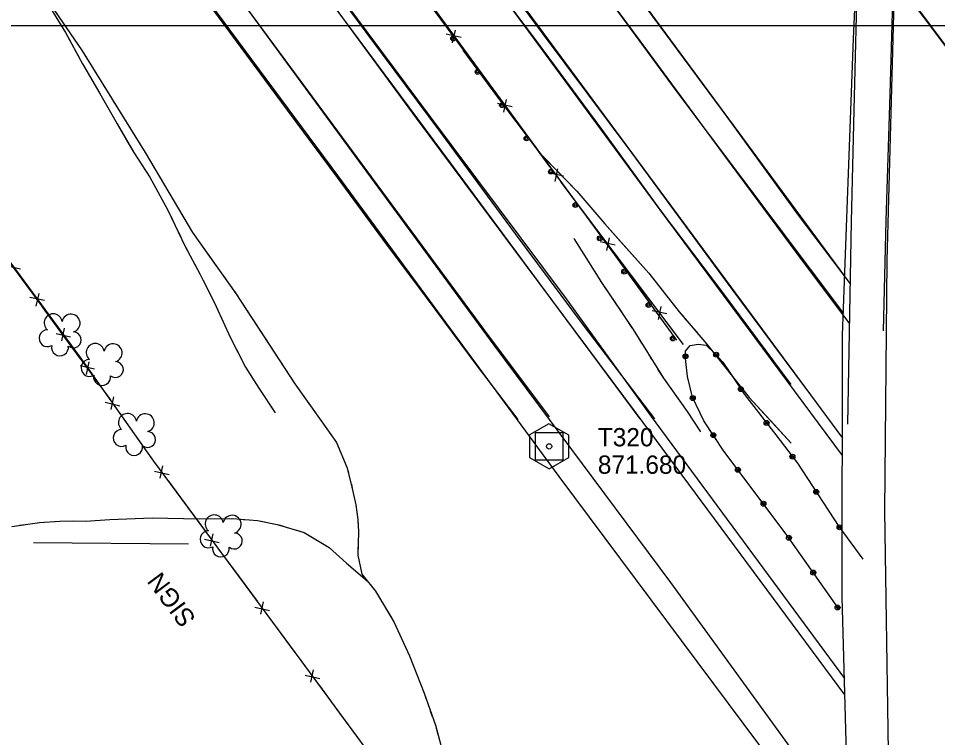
# Model space of a CAD drawing. Extents: x 353423 to 364002, y 127000 to 201942.
# Drawn here: x 361062.1 to 361364.1, y 129766.2 to 130002.3 of the extents above; entities that cross this region are included whole.
import ezdxf

# ---------------------------------------------------------------- set-up
doc = ezdxf.new("R2010")
doc.units = 0
for name, color, linetype in [('E_BMGRD', 7, 'Continuous'), ('E_DTM_SlopeBottom', 7, 'Continuous'), ('E_DTM_SlopeTop', 7, 'Continuous'), ('E_FEN_Generic', 7, 'Continuous'), ('E_LAND_BrushLine', 7, 'Continuous'), ('E_LAND_TreeLine', 7, 'Continuous'), ('E_MISCPROP', 7, 'Continuous'), ('E_STRUCT_WingWall', 7, 'Continuous')]:
    doc.layers.add(name, color=color, linetype=linetype)

msp = doc.modelspace()

# ---------------------------------------------------------------- linework, layer by layer
at = {"layer": 'E_BMGRD'}
for points in [[(361230.04, 129865.58), (361230.04, 129858.19), (361236.5, 129854.46), (361242.89, 129858.13), (361242.89, 129865.46), (361236.37, 129869.18)], [(361231.95, 129857.32), (361231.95, 129866.32), (361240.95, 129866.32), (361240.95, 129857.32)]]:
    msp.add_lwpolyline(points, close=True, dxfattribs=at)
msp.add_circle((361236.45, 129861.82), 0.871, dxfattribs=at)
at = {"layer": 'E_DTM_SlopeBottom'}
for p, q in [((361207.51, 129996.08), (361202.62, 129997.17)), ((361204.76, 129994.27), (361205.66, 129998.47)), ((361221.59, 129971.51), (361222.49, 129975.71)), ((361224.34, 129973.32), (361219.45, 129974.4)), ((361241.16, 129950.57), (361236.27, 129951.65)), ((361238.41, 129948.75), (361239.32, 129952.95)), ((361255.38, 129926.08), (361256.24, 129930.28)), ((361258.11, 129927.92), (361253.21, 129928.95)), ((361058.02, 129921.17), (361062.81, 129920.1)), ((361067.99, 129907.87), (361068.9, 129912)), ((361070.71, 129909.65), (361065.9, 129910.73)), ((361275.16, 129905.33), (361270.26, 129906.36)), ((361272.43, 129903.48), (361273.29, 129907.69)), ((361077.19, 129900.6), (361076.29, 129896.48)), ((361074.49, 129898.82), (361079.28, 129897.75)), ((361087.18, 129887.18), (361082.37, 129888.26)), ((361084.47, 129885.4), (361085.37, 129889.53)), ((361093.41, 129878.04), (361092.44, 129873.94)), ((361090.68, 129876.31), (361095.46, 129875.15)), ((361109.49, 129855.45), (361108.61, 129851.33)), ((361106.8, 129853.67), (361111.6, 129852.61)), ((361126, 129833.12), (361125.11, 129829.01)), ((361123.3, 129831.34), (361128.1, 129830.28)), ((361139.8, 129809.02), (361144.6, 129807.96)), ((361142.5, 129810.8), (361141.61, 129806.68)), ((361158.99, 129788.47), (361158.1, 129784.35)), ((361156.29, 129786.69), (361161.09, 129785.62))]:
    msp.add_line(p, q, dxfattribs=at)
for points in [[(361092.35, 129877.19), (361044.92, 129941.89), (360997.56, 130006.24), (360962.5, 130053.48), (360925.13, 130103.47), (360878.83, 130166.15), (360830.3, 130231.49), (360791.79, 130283.41), (360741.39, 130351.57), (360693.7, 130416.36), (360638.93, 130490.09), (360591.48, 130554.19), (360546.89, 130614.15), (360499.36, 130678.34), (360464.05, 130726.01), (360438.2, 130761.06), (360411.43, 130797.18), (360381.21, 130837.79)], [(360407.27, 130804.74), (360439.73, 130759.75), (360490.26, 130690.73), (360670.73, 130447.81), (360721.87, 130378.76), (360826.04, 130237.28), (360883.23, 130160.42), (360930.64, 130096.44), (361000.73, 130001.84), (361082.18, 129891.3), (361106.51, 129856.97), (361154.89, 129791.52), (361182.92, 129753.46), (361188.88, 129640.57), (361196.9, 129546.21), (361209.22, 129452.29), (361221.13, 129367.62), (361233.6, 129282.65)], [(361280.56, 129895.25), (361246.39, 129940.52), (361192.73, 130013.11), (361149.25, 130071.79), (361085.79, 130158.03), (361032.97, 130229.17), (360984.05, 130295.97), (360926.34, 130374.07), (360876.7, 130440.31), (360808.38, 130531.75)], [(361394.46, 129527.22), (361371.9, 129556.48), (361345.29, 129590.29), (361338.69, 129663.33), (361334.92, 129733.14), (361332.72, 129812.42), (361332.84, 129898.36), (361336.44, 129995.72), (361338.07, 130031.71), (361379.67, 129975.96), (361377.53, 129911.84), (361376.95, 129848.18), (361378.05, 129785.39), (361379.39, 129738.81), (361383.8, 129663.52), (361388.81, 129597.64), (361392.53, 129549.2), (361394.46, 129527.22)], [(361334.58, 129869.07), (361335.8, 129935.63), (361336.7, 129972.19), (361337.9, 130020.86), (361337.99, 130028.55), (361340.14, 130028.39), (361379, 129976.63), (361380.15, 129976.55), (361379.33, 129943.21), (361378.42, 129905.32), (361377.93, 129877.69), (361377.77, 129861.83)], [(361202.81, 129999.46), (361195.98, 130008.71)], [(361212.8, 129985.95), (361206.79, 129994.09)], [(361219.64, 129976.7), (361212.8, 129985.95)], [(361229.63, 129963.19), (361223.62, 129971.33)], [(361236.47, 129953.94), (361229.63, 129963.19)], [(361246.46, 129940.43), (361246.39, 129940.52), (361240.44, 129948.57)], [(361253.39, 129931.25), (361246.46, 129940.43)], [(361263.51, 129917.84), (361257.41, 129925.92)], [(361066.1, 129912.99), (361059.4, 129922.12)], [(361062.62, 129917.85), (361069.31, 129908.77)], [(361270.43, 129908.66), (361263.51, 129917.84)], [(361069.31, 129908.77), (361075.2, 129900.78)], [(361075.88, 129899.65), (361069.99, 129907.69)], [(361280.56, 129895.25), (361274.46, 129903.32)], [(361082.57, 129890.53), (361075.88, 129899.65)], [(361079.09, 129895.5), (361082.18, 129891.3), (361085.69, 129886.35)], [(361085.69, 129886.35), (361091.42, 129878.26)], [(361092.35, 129877.19), (361086.46, 129885.22)], [(361095.22, 129872.9), (361101.74, 129863.7)], [(361101.74, 129863.7), (361106.51, 129856.97), (361107.51, 129855.63)], [(361111.4, 129850.35), (361118.11, 129841.28)], [(361118.11, 129841.28), (361124.01, 129833.3)], [(361127.91, 129828.03), (361134.61, 129818.95)], [(361134.61, 129818.95), (361140.51, 129810.98)], [(361144.41, 129805.7), (361151.11, 129796.63)], [(361151.11, 129796.63), (361154.89, 129791.52), (361157.01, 129788.65)], [(361160.89, 129783.37), (361167.58, 129774.28)], [(361167.58, 129774.28), (361173.47, 129766.29)]]:
    msp.add_lwpolyline(points, dxfattribs=at)
at = {"layer": 'E_DTM_SlopeTop'}
for points in [[(361333.55, 129917.72), (361268.46, 130006.01), (361189.85, 130112.75), (361142.67, 130176.31), (361088.86, 130249.79), (360994.04, 130376.87), (360928.62, 130465.05), (360871.56, 130543.5), (360815.21, 130618.95), (360766.71, 130684.28), (360721.66, 130745.05), (360677.21, 130805.9), (360595.4, 130915.9), (360546.5, 130984.06), (360499.99, 131045.42), (360426.96, 131144.04)], [(360419.47, 131139.59), (360478.07, 131059.84), (360541.82, 130973.68), (360588.71, 130910.37), (360647.11, 130831.47), (360699.04, 130761.76), (360750.66, 130691.62), (360805.87, 130616.86), (360864.14, 130537.84), (360910.27, 130475.6), (360951.2, 130420.07), (361004.77, 130348.23), (361046.61, 130292.04), (361097.13, 130223.94), (361149.43, 130153.39), (361185.11, 130104.98), (361238.11, 130033), (361245.88, 130022.49), (361278.08, 129978.64), (361333.1, 129905.4)], [(361334.82, 129736.64), (361276.43, 129817.07), (361218.41, 129895.06), (361173.92, 129955.59), (361116.6, 130033.88), (361057.88, 130112.91), (361005.23, 130183.79), (360919.7, 130299.92), (360859.57, 130381.04), (360802.73, 130458.17), (360712.34, 130579.92), (360650.2, 130664.74), (360583.26, 130754.37), (360522.68, 130834.6), (360443.16, 130936.49), (360381.32, 131015.53), (360355.42, 131048.77)], [(360359.06, 131031.63), (360412.77, 130962.23), (360456.51, 130906.46), (360514.58, 130829.11), (360575.61, 130749.78), (360615.66, 130696.58), (360651.09, 130648.19), (360678.79, 130610.26), (360711.14, 130566.37), (360768.38, 130488.8), (360811.24, 130431.97), (360853.39, 130374.54), (360875.99, 130343.44), (360911.98, 130295.27), (360943.46, 130251.36), (360971.6, 130213.46), (361000.8, 130174.05), (361030.19, 130135.22), (361061.21, 130091.97), (361110.81, 130026.56), (361166.93, 129950.76), (361239.61, 129851.93), (361335.43, 129723.6)], [(361335.19, 129902.03), (361317.97, 129925.09), (361294.2, 129957.22), (361266.66, 129994.48), (361242.03, 130027.81), (361217.11, 130061.23), (361186.78, 130102.37), (361155.57, 130144.32), (361126.8, 130183.16), (361098.06, 130221.84), (361070.02, 130259.76), (361036.43, 130304.8), (361006.19, 130345.98), (360970.52, 130394.27), (360936.12, 130440.54), (360901.22, 130487.47), (360871.26, 130528.04), (360838.83, 130571.83), (360808.58, 130612.92), (360780.05, 130651.51), (360745.78, 130697.86), (360715, 130739.66), (360684.42, 130781.1), (360659.61, 130814.18)], [(360539.14, 130812.53), (360565.51, 130777.84), (360593.87, 130739.91), (360625.54, 130697.03), (360652.65, 130660.22), (360685.53, 130616.09), (360714.56, 130576.84), (360749.27, 130530.18), (360775.57, 130494.65), (360810.61, 130447.18), (360838.14, 130409.72), (360879.43, 130354.21), (360906.49, 130317.48), (360944.28, 130266.52), (360972.83, 130227.69), (361006.65, 130182.14), (361037.04, 130141.05), (361070.51, 130095.92), (361098.26, 130058.32), (361129.55, 130016.03), (361157.08, 129978.62), (361188.2, 129936.52), (361215.22, 129899.89), (361236.43, 129871.54)], [(360570.32, 130810.78), (360600.22, 130770.91), (360638.59, 130718.65), (360671.71, 130673.89), (360707.05, 130626.12), (360742.48, 130578.27), (360774.17, 130535.49), (360800.97, 130499.08), (360825.44, 130466.23), (360849.91, 130433.42), (360876.06, 130397.89), (360904.66, 130359.17), (360936.36, 130316.65), (360963.75, 130279.7), (360997.86, 130233.57), (361031.14, 130188.46), (361063.99, 130144.35), (361101.47, 130093.76), (361133.47, 130050.11), (361168.56, 130002.53), (361203.91, 129954.89), (361239.46, 129906.99), (361266.3, 129870.87)], [(360770.85, 130623.99), (360920.54, 130421.12), (360968.13, 130357.32), (361021.12, 130285.55), (361062.98, 130229.08), (361129.94, 130138.98), (361193.82, 130052.53), (361225.46, 130009.93), (361276.5, 129940.65), (361332.79, 129864.55)], [(360809.17, 130495.51), (360846.5, 130444.78), (360882.4, 130395.79), (360941.46, 130316.09), (360973.72, 130272.7), (361030.47, 130195.64), (361062.59, 130152.28), (361119.78, 130075.34), (361156.76, 130024.57), (361197.37, 129970), (361242.06, 129910.29), (361269.99, 129871.58), (361333.46, 129785.62)], [(361333.61, 129780.26), (361265.17, 129872.62), (361192.86, 129969.59), (361136.86, 130045.95), (361055.9, 130154.85), (360997.16, 130234.51), (360938.4, 130314.25), (360864.11, 130414.93), (360812.38, 130484.47)], [(361320.8, 129880.93), (361296.29, 129913.9), (361263.68, 129958.06), (361234.3, 129997.51), (361207.91, 130033.09), (361178.81, 130072.84), (361153.28, 130107.14), (361123.39, 130147.5), (361095.85, 130184.68), (361064.34, 130227.06), (361035.35, 130266.14), (361005.51, 130306.49), (360976.86, 130345.11), (360946.73, 130385.87), (360915.39, 130428.25), (360885.77, 130468.28)], [(361364.15, 130463.8), (361361.59, 130388.23), (361359.32, 130320.57), (361356.86, 130245.77), (361354.69, 130183.63), (361352.25, 130086.51), (361349.91, 130015.95), (361347.38, 129922.87), (361346.61, 129840.6), (361347.83, 129761.6), (361352.72, 129668.25), (361359.38, 129573.66), (361368.71, 129484.13)], [(360792.03, 130456.94), (360810.78, 130431.34), (360829.91, 130405.6), (360852.4, 130375.06), (360875.72, 130343.54), (360899.12, 130311.93), (360923, 130279.49), (360943.58, 130251.93), (360971.77, 130213.66), (361001.07, 130173.94), (361030.07, 130135.21), (361061.27, 130093.22), (361089.96, 130054.2), (361110.35, 130026.4), (361125.86, 130005.3), (361150.45, 129972.15), (361166.88, 129950.07), (361181.73, 129929.81), (361196.39, 129910.21), (361212.86, 129888.17), (361226.12, 129870.67)], [(361315.93, 129882.16), (361293.84, 129911.88), (361273.17, 129939.3), (361253.73, 129966), (361232.26, 129994.92), (361212.38, 130021.46), (361191.99, 130049.3), (361172.21, 130076.18), (361149.26, 130107.13), (361127.42, 130136.54), (361104.58, 130168), (361082.65, 130197.4), (361058.78, 130229.15), (361037.29, 130258.72), (361014.89, 130289.35), (360990.9, 130321.1), (360964.02, 130357.74), (360938.89, 130391.55), (360917.5, 130420.34), (360910.02, 130430.06), (360903.76, 130437.94), (360889.26, 130454.61)], [(360841.54, 130450.25), (360860.15, 130425.31), (360880.25, 130397.9), (360900.17, 130371.31), (360917.16, 130348.06), (360937.39, 130320.73), (360957.17, 130293.76), (360972.69, 130273.01), (360996.25, 130240.92), (361018.29, 130211.17), (361040.01, 130181.94), (361060.38, 130154.78), (361080.04, 130128.16), (361097.27, 130104.56), (361117.19, 130077.84), (361139.93, 130047.25), (361157.98, 130022.58), (361181.63, 129990.53), (361200.8, 129964.87), (361225.35, 129931.59), (361247.64, 129901.57), (361271.03, 129870.81)], [(361335.43, 129915.2), (361318.32, 129937.74), (361294.9, 129970), (361272.87, 129999.89), (361246.92, 130035.01), (361222.25, 130068.43), (361195.24, 130105.46), (361170.48, 130138.89), (361140.99, 130178.92), (361116.11, 130212.79), (361091.54, 130246.75), (361068.94, 130276.61), (361043.39, 130310.64), (361020.48, 130341.85), (360997.65, 130373.15), (360974.98, 130403.77), (360946.02, 130442.35)], [(361332.78, 129858.83), (361272.95, 129939.51), (361217.84, 130014.35), (361160.82, 130091.59), (361106.47, 130164.46), (361052.75, 130237.37), (360984.41, 130329.68), (360919.87, 130416.78), (360905.62, 130436.19)], [(361346.33, 129899.77), (361347.17, 129935.9), (361348.45, 129977.39), (361349.59, 130015.92)]]:
    msp.add_lwpolyline(points, dxfattribs=at)
at = {"layer": 'E_FEN_Generic'}
for centre, radius, start, end in [((361073.57, 129902.36), 2.97, 8.3641, 229.598), ((361079.42, 129902.24), 2.97, 286.0149, 168.9882), ((361071.7, 129897.32), 2.78, 91.335, 299.108), ((361080.18, 129896.77), 2.61, 230.7202, 88.6528), ((361075.78, 129894.31), 2.78, 168.012, 9.0231), ((361087.38, 129892.62), 2.97, 8.3641, 229.598), ((361093.23, 129892.5), 2.97, 286.0149, 168.9882), ((361085.51, 129887.57), 2.78, 91.335, 299.108), ((361093.99, 129887.03), 2.61, 230.7202, 88.6528), ((361089.59, 129884.57), 2.78, 168.012, 9.0231), ((361097.95, 129869.63), 2.97, 8.3641, 229.598), ((361103.8, 129869.52), 2.97, 286.0149, 168.9882), ((361096.08, 129864.59), 2.78, 91.335, 299.108), ((361104.56, 129864.05), 2.61, 230.7202, 88.6528), ((361100.16, 129861.59), 2.78, 168.012, 9.0231), ((361126.45, 129836.34), 2.97, 8.3641, 229.598), ((361132.31, 129836.22), 2.97, 286.0149, 168.9882), ((361124.59, 129831.3), 2.78, 91.335, 299.108), ((361133.07, 129830.75), 2.61, 230.7202, 88.6528), ((361128.66, 129828.3), 2.78, 168.012, 9.0231)]:
    msp.add_arc(centre, radius, start, end, dxfattribs=at)
at = {"layer": 'E_LAND_BrushLine'}
msp.add_line((361118.05, 129829.69), (361067.05, 129830.11), dxfattribs=at)
at = {"layer": 'E_LAND_TreeLine'}
msp.add_line((360000, 130000), (363500, 130000), dxfattribs=at)
at = {"layer": 'E_MISCPROP'}
for points in [[(361278.44, 129896.66), (361257.2, 129925.87), (361196.67, 130008.28), (361135.58, 130090.48), (361077.01, 130169.81), (361020.19, 130246.45), (360959.7, 130328.59), (360910.54, 130394.3), (360868.77, 130451.11), (360840.07, 130489.69), (360808.04, 130532.66)], [(361278.44, 129896.66), (361257.2, 129925.87), (361196.67, 130008.28), (361135.58, 130090.48), (361077.01, 130169.81), (361020.19, 130246.45), (360959.7, 130328.59), (360910.54, 130394.3), (360868.77, 130451.11), (360840.07, 130489.69), (360808.04, 130532.66)], [(361331.79, 129808.1), (361314.35, 129833.04), (361293.86, 129860.24), (361287.3, 129870.21), (361283.51, 129877.93), (361281.95, 129884.77), (361281.28, 129890.68), (361281.2, 129893.08), (361282.8, 129894.93), (361285.46, 129895.42), (361287.99, 129895), (361290.93, 129892.35), (361293.54, 129889.45), (361295.76, 129886.04), (361300.59, 129878.88), (361310.93, 129865.57), (361318.04, 129856.26), (361331.65, 129835.47), (361339.48, 129824.81)], [(361331.79, 129808.1), (361314.35, 129833.04), (361293.86, 129860.24), (361287.3, 129870.21), (361283.51, 129877.93), (361281.95, 129884.77), (361281.28, 129890.68), (361281.2, 129893.08), (361282.8, 129894.93), (361285.46, 129895.42), (361287.99, 129895), (361290.93, 129892.35), (361293.54, 129889.45), (361295.76, 129886.04), (361300.59, 129878.88), (361310.93, 129865.57), (361318.04, 129856.26), (361331.65, 129835.47), (361332.75, 129833.97)]]:
    msp.add_lwpolyline(points, dxfattribs=at)
for centre, radius in [((361204.93, 129995.7), 0.79), ((361204.9, 129995.74), 0.398), ((361212.96, 129984.77), 0.79), ((361212.93, 129984.8), 0.398), ((361220.99, 129973.84), 0.79), ((361220.96, 129973.87), 0.398), ((361229.02, 129962.91), 0.79), ((361228.99, 129962.94), 0.398), ((361237.04, 129951.98), 0.79), ((361237.02, 129952.01), 0.398), ((361245.07, 129941.04), 0.79), ((361245.05, 129941.08), 0.398), ((361253.1, 129930.11), 0.79), ((361253.08, 129930.15), 0.398), ((361261.1, 129919.16), 0.79), ((361261.08, 129919.2), 0.398), ((361269.08, 129908.2), 0.79), ((361269.05, 129908.23), 0.398), ((361277.06, 129897.23), 0.79), ((361277.03, 129897.26), 0.398), ((361281.26, 129891.38), 0.812), ((361281.26, 129891.38), 0.409), ((361291.31, 129891.92), 0.812), ((361291.31, 129891.92), 0.409), ((361299.43, 129880.61), 0.812), ((361283.64, 129877.67), 0.812), ((361283.64, 129877.67), 0.409), ((361299.43, 129880.61), 0.409), ((361307.87, 129869.51), 0.812), ((361307.87, 129869.51), 0.409), ((361290.4, 129865.5), 0.812), ((361290.4, 129865.5), 0.409), ((361316.37, 129858.44), 0.812), ((361316.37, 129858.44), 0.409), ((361298.47, 129854.12), 0.812), ((361298.47, 129854.12), 0.409), ((361324.18, 129846.89), 0.812), ((361324.18, 129846.89), 0.409), ((361306.87, 129842.98), 0.812), ((361306.87, 129842.98), 0.409), ((361331.83, 129835.22), 0.812), ((361331.83, 129835.22), 0.409), ((361315.22, 129831.81), 0.812), ((361315.22, 129831.81), 0.409), ((361323.21, 129820.37), 0.812), ((361323.21, 129820.37), 0.409), ((361331.2, 129808.94), 0.812), ((361331.2, 129808.94), 0.409)]:
    msp.add_circle(centre, radius, dxfattribs=at)
at = {"layer": 'E_STRUCT_WingWall'}
for points in [[(361065.33, 130017.61), (361083.05, 129991.7), (361103.77, 129958.31), (361119.27, 129932.02), (361133.58, 129911.96), (361152.88, 129882.3), (361161.04, 129870.91), (361166.6, 129863.08), (361170.06, 129855.03), (361171.48, 129849.41), (361172.96, 129842.59), (361173.59, 129837.78), (361173.82, 129833.71), (361173.57, 129826.06), (361174.96, 129819.82), (361179.41, 129814.32), (361185.5, 129804.19), (361190.59, 129793.08), (361195.39, 129780.74), (361199.08, 129770.26), (361202.52, 129757.63)], [(361068.5, 130012.98), (361083.05, 129991.7), (361084.82, 129988.85)], [(361071.23, 130007.99), (361077.62, 129997.66), (361083.23, 129987.4), (361088.87, 129977.66), (361094.54, 129967.65), (361100.05, 129958.26), (361105.31, 129950.16), (361111.26, 129939.38), (361116.94, 129927.44), (361121.87, 129918.28), (361127.13, 129907.77), (361131.68, 129897.68), (361136.75, 129887.79), (361141.15, 129880.92), (361146.47, 129872.77)], [(361075.03, 130001.84), (361076.08, 130000.14)], [(361078.13, 129996.71), (361079.09, 129994.96)], [(361081.02, 129991.45), (361081.98, 129989.7)], [(361208.14, 129991.89), (361219.47, 129976.44), (361233.32, 129958.2), (361245.56, 129945.6), (361254.73, 129934.92), (361269.16, 129918.63), (361279.16, 129906.02), (361288.21, 129895.39), (361302.21, 129877.82), (361315.92, 129862.88)], [(361208.14, 129991.89), (361219.47, 129976.44), (361225.42, 129968.6)], [(361083.92, 129986.2), (361088.87, 129977.66), (361094.54, 129967.65), (361098.4, 129961.07)], [(361086.93, 129985.43), (361087.99, 129983.73)], [(361090.11, 129980.31), (361091.17, 129978.6)], [(361093.29, 129975.19), (361094.35, 129973.49)], [(361096.47, 129970.07), (361103.77, 129958.31), (361111.53, 129945.14)], [(361227.84, 129965.42), (361229.05, 129963.82)], [(361098.4, 129961.07), (361100.05, 129958.26), (361105.31, 129950.16), (361111.26, 129939.38), (361112.88, 129935.98)], [(361231.47, 129960.64), (361232.67, 129959.04)], [(361235.36, 129956.09), (361236.76, 129954.66)], [(361239.55, 129951.79), (361245.56, 129945.6), (361254.73, 129934.92), (361258.9, 129930.21)], [(361111.53, 129945.14), (361119.27, 129932.02), (361127.34, 129920.71)], [(361114.6, 129932.37), (361115.46, 129930.56)], [(361244.54, 129930.07), (361253.62, 129915.61), (361264.04, 129900.15), (361273.97, 129884.15), (361281.84, 129873.29), (361286.19, 129866.58)], [(361244.54, 129930.07), (361253.62, 129915.61), (361260.28, 129905.72)], [(361258.9, 129930.21), (361269.16, 129918.63), (361277.57, 129908.03)], [(361117.2, 129926.96), (361118.15, 129925.2)], [(361120.04, 129921.68), (361120.99, 129919.92)], [(361129.67, 129917.43), (361130.84, 129915.8)], [(361122.83, 129916.36), (361127.13, 129907.77), (361131.68, 129897.68), (361135.47, 129890.27)], [(361133.17, 129912.53), (361133.58, 129911.96), (361134.29, 129910.86)], [(361136.48, 129907.49), (361137.58, 129905.81)], [(361139.77, 129902.44), (361152.88, 129882.3), (361155.85, 129878.16)], [(361262.52, 129902.41), (361263.64, 129900.75)], [(361280.1, 129904.93), (361281.39, 129903.4)], [(361283.98, 129900.36), (361285.28, 129898.83)], [(361265.77, 129897.36), (361266.82, 129895.66)], [(361287.87, 129895.79), (361288.21, 129895.39), (361289.13, 129894.23)], [(361135.47, 129890.27), (361136.75, 129887.79), (361141.15, 129880.92), (361146.47, 129872.77)], [(361268.93, 129892.26), (361269.99, 129890.57)], [(361291.62, 129891.1), (361302.21, 129877.82), (361310.33, 129868.97)], [(361272.1, 129887.17), (361273.97, 129884.15), (361281.84, 129873.29), (361286.19, 129866.58)], [(361155.85, 129878.16), (361161.04, 129870.91), (361166.6, 129863.08), (361170.06, 129855.03), (361170.51, 129853.26)], [(361310.33, 129868.97), (361315.92, 129862.88)], [(361171.49, 129849.36), (361171.92, 129847.4)], [(361172.77, 129843.47), (361172.96, 129842.59), (361173.1, 129841.49)], [(361059.96, 129835.54), (361069.06, 129836.85), (361075.75, 129837.26), (361080.14, 129837.39), (361084.19, 129837.28), (361092.18, 129837.83), (361106.03, 129838.4), (361121.52, 129838.02), (361132.43, 129838.11), (361140.62, 129837.53), (361147.17, 129836.19), (361155.99, 129833.58), (361164.16, 129828.65), (361169.86, 129823.46), (361176.74, 129817.62)], [(361062.49, 129835.9), (361064.46, 129836.19)], [(361068.4, 129836.76), (361069.06, 129836.85), (361070.38, 129836.93)], [(361074.35, 129837.17), (361075.75, 129837.26), (361080.14, 129837.39), (361084.19, 129837.28), (361092.18, 129837.83), (361103.18, 129838.28)], [(361103.18, 129838.28), (361106.03, 129838.4), (361121.52, 129838.02), (361132.04, 129838.11)], [(361136.02, 129837.86), (361138, 129837.71)], [(361141.95, 129837.26), (361143.9, 129836.86)], [(361147.79, 129836.01), (361149.7, 129835.45)], [(361173.61, 129837.51), (361173.72, 129835.5)], [(361153.52, 129834.32), (361155.99, 129833.58), (361164.16, 129828.65), (361169.86, 129823.46), (361176.74, 129817.62)], [(361173.75, 129831.49), (361173.57, 129826.06), (361174.96, 129819.82), (361179.41, 129814.32), (361184.68, 129805.55)], [(361184.68, 129805.55), (361185.5, 129804.19), (361190.59, 129793.08), (361195.39, 129780.74), (361196.08, 129778.78)], [(361197.41, 129774.99), (361198.08, 129773.09)], [(361199.34, 129769.28), (361199.87, 129767.34)]]:
    msp.add_lwpolyline(points, dxfattribs=at)

# ---------------------------------------------------------------- texts
at = {"layer": 'E_BMGRD'}
for s, p in [('T320', (361252.45, 129861.82)), ('871.680', (361252.45, 129852.82))]:
    msp.add_text(s, height=6, dxfattribs=at).set_placement(p)
at = {"layer": 'E_LAND_BrushLine'}
msp.add_text('SIGN', height=6, rotation=126.7563, dxfattribs=at).set_placement((361120.67, 129805.35))

doc.saveas('drawing.dxf')
